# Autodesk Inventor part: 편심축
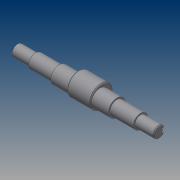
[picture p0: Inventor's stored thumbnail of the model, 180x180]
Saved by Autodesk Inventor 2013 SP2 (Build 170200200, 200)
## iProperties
Created: 2014-12
Part Number: 편심축
Material: Generic
Document SubType Name: Modeling
Designer: user
Density: 1 g/cm^3
Author: user
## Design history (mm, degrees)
sketch "스케치1"
  geometry: L1 (-75.5, 0)-(75.5, 0); L2 (-75.5, 0)-(-75.5, 6); L3 (-75.5, 6)-(-55.5, 6); L4 (-55.5, 6)-(-55.5, 7.5); L5 (-55.5, 7.5)-(-30.5, 7.5); L6 (-30.5, 7.5)-(-30.5, 9); L7 (-30.5, 9)-(-12.5, 9); L8 (12.5, 9)-(30.5, 9); L9 (30.5, 9)-(30.5, 7.5); L10 (30.5, 7.5)-(55.5, 7.5); L11 (55.5, 7.5)-(55.5, 6); L12 (55.5, 6)-(75.5, 6); L13 (75.5, 6)-(75.5, 0); L14 (-12.5, 9)-(12.5, 9); 3 further points
  constraints: 28 end point, 9 parallel, 2 coincident, 2 perpendicular, 1 collinear, 1 horizontal, 1 midpoint
  dimensions: "d0" = 151 distance of L1.start L1.end; "d1" = 12 diameter of L3 L1; "d2" = 15 diameter of L5 L1; "d3" = 18 diameter of L7 L1; "d4" = 12 diameter of L12 L1; "d5" = 15 diameter of L10 L1; "d6" = 18 diameter of L8 L1; "d8" = 20 distance of L2.end L3.end; "d9" = 25 distance of L4.end L5.end; "d10" = 18 distance of L6.end L7.end; "d11" = 18 distance of L8.start L8.end; "d12" = 25 distance of L9.end L10.end; "d13" = 20 distance of L11.end L12.end
revolve "회전1" stored, may be unused: angle "d21" = 90 deg
sketch "스케치2"
  geometry: L1 (-12.5, 2)-(12.5, 2); L2 (-12.5, 2)-(-12.5, 14); L3 (-12.5, 14)-(11.817, 14); L4 (11.817, 14)-(12.5, 14); L5 (12.5, 14)-(12.5, 2); 3 further points
  constraints: 10 end point, 2 perpendicular, 1 coincident, 1 collinear, 1 horizontal, 1 midpoint, 1 parallel, 1 vertical alignment
  dimensions: "d23" = 25 distance of L1.start L1.end; "d24" = 2 distance from line of L1 point (0, 0); "d25" = 12 distance between parallel lines of L3 L1
revolve "회전3" sketch "스케치2" stored, may be unused: angle "d26" = 90 deg
chamfer "모따기1" distance "d27" = 1; stored, may be unused: second distance "d28" = 2, angle "d29" = 45 deg
node "작업 평면1"
sketch "스케치3"
  geometry: L1 (10, 5)-(10, -5) reference; L2 (10, -2.5)-(-1.5, -2.5); L3 (-4, 0)-(-4, 0); L4 (-1.5, 2.5)-(10, 2.5); L5 (10, 2.5)-(10, -2.5); A1 r 2.5 centre (-1.5, 0) between (-1.5, 2.5) and (-4, 0); A2 r 2.5 centre (-1.5, 0) between (-4, 0) and (-1.5, -2.5); 5 further points
  constraints: 8 end point, 5 point on line, 4 point on circle, 4 tangent, 2 centre point, 2 midpoint, 2 parallel, 1 concentric, 1 horizontal, 1 horizontal alignment, 1 perpendicular
  dimensions: "d30" = 14 distance of point (-4, 2.5) L4.end; "d31" = 5 distance of point (-4, -2.5) point (-4, 2.5); "d32" = 2.5 radius of A1
extrude "돌출1" cut sketch "스케치3" distance "d33" = 3; taper "d34" = 0 deg
node "솔리드1"
mirror "대칭1"
